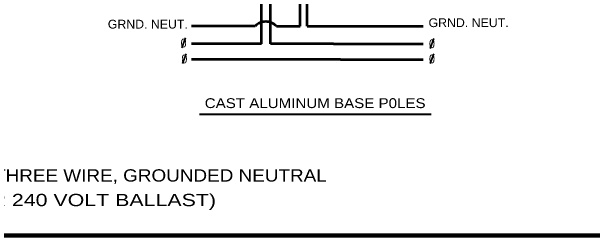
# Model space of a CAD drawing. Extents: x -217 to 639, y -295 to 249.
# Drawn here: x 38.9 to 237.5, y -283.7 to -207.2 of the extents above; entities that cross this region are included whole.
import ezdxf
from ezdxf.enums import TextEntityAlignment as Align

# ---------------------------------------------------------------- set-up
doc = ezdxf.new("R2010")
doc.units = 0
doc.header["$LTSCALE"] = 1.2
doc.layers.add('1', color=7, linetype='Continuous', lineweight=53)

msp = doc.modelspace()

# ---------------------------------------------------------------- linework, layer by layer
at = {"layer": '1'}
for p, q in [((124.431, -218.202), (124.431, -154.477)), ((127.431, -218.202), (127.431, -154.477)), ((137.631, -212.204), (137.631, -154.538)), ((140.031, -212.204), (140.031, -154.538)), ((122.255, -212.204), (100.431, -212.204)), ((129.498, -212.204), (137.631, -212.204)), ((140.031, -212.204), (179.631, -212.204)), ((124.431, -218.202), (100.431, -218.202)), ((148.971, -218.202), (127.431, -218.202)), ((148.971, -218.202), (179.631, -218.202)), ((151.379, -223.604), (100.431, -223.604)), ((151.379, -223.604), (179.631, -223.604))]:
    msp.add_line(p, q, dxfattribs=at)
at = {"layer": '1', "lineweight": 35}
for p, q in [((98.336, -216.22), (97.099, -219.619)), ((183.262, -216.463), (182.025, -219.862)), ((98.579, -221.616), (97.342, -225.015)), ((183.262, -221.616), (182.025, -225.015))]:
    msp.add_line(p, q, dxfattribs=at)
at = {"layer": '1', "lineweight": 40}
msp.add_line((103.121, -242.333), (182.337, -242.333), dxfattribs=at)
at = {"layer": '1', "lineweight": 158}
msp.add_line((632.039, -283.701), (-159.561, -283.701), dxfattribs=at)
at = {"layer": '1'}
for start, end in [(44.31179, 136.66815), (43.26875, 43.74948)]:
    msp.add_arc((125.863, -215.683), 5.031, start, end, dxfattribs=at)

# ---------------------------------------------------------------- texts
for s, width, p in [('GRND. NEUT.', 1.05, (71.82, -213.021)), ('GRND. NEUT.', 1.05, (181.502, -212.526)), ('0', 0.9, (96.746, -219.474)), ('0', 0.9, (181.669, -219.721)), ('0', 0.9, (96.994, -224.921)), ('0', 0.9, (181.669, -224.921))]:
    msp.add_text(s, height=3, dxfattribs=dict(at, width=width)).set_placement(p)
for s, height, width, p in [('CAST ALUMINUM BASE P0LES', 3.36, 1.15, (142.729, -240.199)), ('120 OR 240 VOLTS, THREE WIRE, GROUNDED NEUTRAL', 4.2, 1.15, (59.112, -265.317)), ('(120 OR 240 VOLT BALLAST)', 4.2, 1.3, (59.112, -273.717))]:
    msp.add_text(s, height=height, dxfattribs=dict(at, width=width)).set_placement(p, align=Align.CENTER)

doc.saveas('drawing.dxf')
